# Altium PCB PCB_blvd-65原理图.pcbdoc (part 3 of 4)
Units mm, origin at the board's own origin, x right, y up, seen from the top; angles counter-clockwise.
Board outline 317.5 x 107.96 mm, 2 copper layers (Top Layer, Bottom Layer); 180 components, 111 nets, 404 pads, 231 vias.
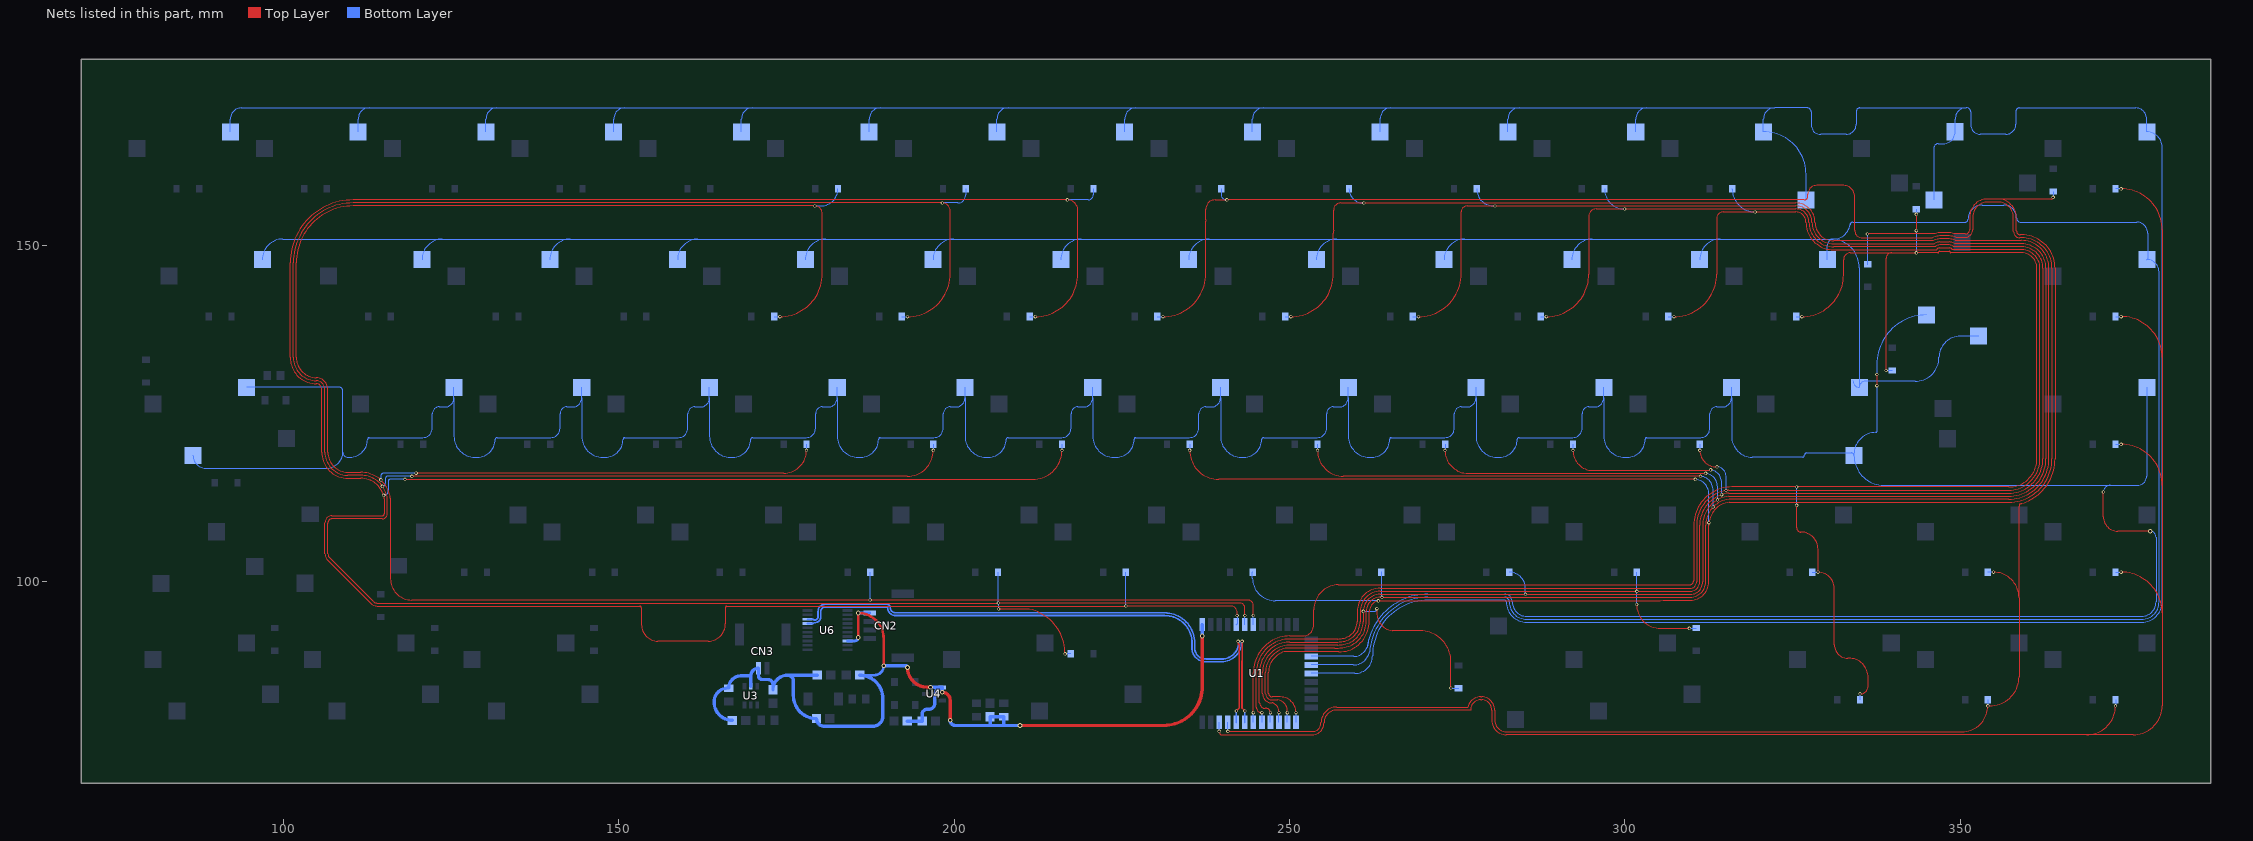
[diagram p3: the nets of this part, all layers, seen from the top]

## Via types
v1: diameter 0.5, hole 0.3, Top Layer to Bottom Layer, 198 vias
v2: diameter 0.7, hole 0.4, Top Layer to Bottom Layer, 33 vias

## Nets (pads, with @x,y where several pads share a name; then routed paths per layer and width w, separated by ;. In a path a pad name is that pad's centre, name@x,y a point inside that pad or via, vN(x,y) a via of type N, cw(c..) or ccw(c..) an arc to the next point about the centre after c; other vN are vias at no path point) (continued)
COL5: D5.2 D27.2 D43.2 D59.2 U1.7 | length 369.7
  Top Layer w0.1: 102.836,131.155 cw(c104.902,133.35) 101.887,133.35 101.887,147.447 cw(c110.385,147.447) 110.385,155.945 v1(179.208,155.945) cw(c179.208,154.813) 180.34,154.813 180.34,145.796 cw(c173.99,145.796) v1(173.99,139.446) ; 102.836,131.155 ccw(c104.902,133.35) 104.902,130.335 cw(c104.902,128.651) 106.586,128.655 cw(c104.046,128.651) 106.586,128.651 106.586,119.253 ccw(c109.601,119.253) 109.601,116.238 111.506,116.238 cw(c111.506,111.76) 113.037,115.969 cw(c111.506,111.76) 113.383,115.826 cw(c111.506,111.76) 113.689,115.671 cw(c111.506,111.76) v1(114.497,115.093) cw(c111.379,111.704) 115.779,113.065 cw(c111.379,111.704) 115.94,112.341 115.94,100.374 ccw(c119.126,100.374) 119.126,97.188 v1(187.476,97.188) 243.807,97.188 cw(c243.807,96.382) 244.613,96.382 v1(244.613,94.869) ; v1(119.761,116.089) 174.551,116.089 ccw(c174.551,119.507) v1(177.969,119.507)
  Bottom Layer w0.1: v1(114.497,115.093) 114.497,115.651 cw(c114.935,115.651) 114.935,116.089 v1(119.761,116.089) ; D27.2@173.143,139.446 v1(173.99,139.446) ; v1(177.969,119.507) D43.2@177.969,120.396 ; v1(179.208,155.945) 180.117,155.945 ccw(c180.117,158.496) D5.2@182.668,158.496 ; v1(187.476,97.188) 187.476,101.333 cw(c187.489,101.333) D59.2@187.489,101.346 ; U1.7@244.613,93.533 v1(244.613,94.869)
COL6: D6.2 D26.2 D42.2 D58.2 D74.2 U1.6 | length 439.9
  Top Layer w0.1: 106.136,128.651 106.136,119.253 ccw(c109.601,119.253) 109.468,115.791 ccw(c109.601,119.253) 109.601,115.788 111.506,115.788 cw(c111.506,111.76) 112.883,115.546 cw(c111.506,111.76) 113.194,115.418 cw(c111.506,111.76) 113.402,115.314 cw(c111.506,111.76) 113.469,115.278 cw(c111.506,111.76) 114.194,114.76 cw(c111.379,111.704) v1(114.742,114.145) cw(c111.379,111.704) 115.349,112.932 cw(c111.379,111.704) 115.49,112.308 115.49,110.029 cw(c114.739,110.029) 114.739,109.278 107.188,109.278 ccw(c107.188,108.712) 106.636,108.838 ccw(c107.823,108.654) 106.622,108.654 106.622,104.054 ccw(c107.313,104.054) 106.825,103.566 113.468,96.922 ccw(c113.912,97.367) 113.912,96.738 v1(206.589,96.738) 242.606,96.738 cw(c242.606,96.001) 243.343,96.001 v1(243.343,94.869) ; 106.136,128.654 ccw(c104.902,128.651) 104.902,129.885 cw(c104.902,133.35) 102.528,130.827 cw(c104.902,133.35) 101.437,133.35 101.437,147.447 cw(c110.385,147.447) 110.385,156.395 v1(198.241,156.395) cw(c198.241,155.246) 199.39,155.246 199.39,145.796 cw(c193.04,145.796) v1(193.04,139.446) ; v1(119.126,115.639) 193.024,115.639 ccw(c193.024,119.507) v1(196.892,119.507) ; v1(206.629,95.838) 211.211,95.838 cw(c209.677,89.154) v1(216.535,89.154)
  Bottom Layer w0.1: v1(114.742,114.145) ccw(c114.742,114.592) 115.189,114.592 115.189,115.316 cw(c115.512,115.316) 115.512,115.639 v1(119.126,115.639) ; D26.2@192.193,139.446 v1(193.04,139.446) ; v1(196.892,119.507) D42.2@196.892,120.396 ; v1(198.241,156.395) 200.539,156.395 ccw(c200.539,157.574) 201.427,156.799 ; D6.2@201.718,158.496 201.718,157.607 ; D58.2@206.539,101.346 cw(c206.539,101.296) 206.589,101.296 v1(206.589,96.738) cw(c206.589,96.698) 206.629,96.698 v1(206.629,95.838) ; v1(216.535,89.154) D74.2@217.383,89.154 ; U1.6@243.343,93.533 v1(243.343,94.869) ; 201.427,156.799 ccw(c200.539,157.574) 201.718,157.574 201.718,157.607 ; 201.427,156.799 ccw(c200.448,157.607) 201.718,157.607
COL7: D7.2 D25.2 D41.2 D57.2 U1.5 | length 475.6
  Top Layer w0.1: 105.686,128.651 105.686,119.253 ccw(c109.601,119.253) 109.601,115.338 111.506,115.338 cw(c111.506,111.76) 112.729,115.123 cw(c111.506,111.76) 113.006,115.009 cw(c111.506,111.76) 113.19,114.917 cw(c111.506,111.76) 113.25,114.885 cw(c111.506,111.76) 113.518,114.719 ; 105.686,128.653 ccw(c104.902,128.651) 104.902,129.435 cw(c104.902,133.35) 102.219,130.499 cw(c104.902,133.35) 100.987,133.35 100.987,147.447 cw(c110.385,147.447) 110.385,156.845 v1(216.875,156.845) cw(c216.875,155.28) 218.44,155.28 218.44,145.796 cw(c212.09,145.796) v1(212.09,139.446) ; v1(118.11,115.189) 211.751,115.189 ccw(c211.751,119.507) v1(216.069,119.507) ; v1(242.189,94.869) 242.189,95.388 ccw(c241.289,95.388) 241.289,96.288 v1(225.603,96.288) 166.12,96.288 ccw(c166.12,96.063) 165.895,96.063 165.895,93.631 cw(c163.322,93.631) 163.322,91.059 155.829,91.059 cw(c155.829,93.527) 153.362,93.527 153.362,96.043 ccw(c153.117,96.043) 153.117,96.288 113.993,96.288 cw(c113.993,97.646) 113.033,96.686 106.547,103.172 cw(c107.451,104.076) 106.172,104.076 106.172,108.712 cw(c107.188,108.712) 107.188,109.728 114.694,109.728 ccw(c114.694,110.075) 115.04,110.075 115.04,112.275 ; 113.518,114.719 cw(c111.506,111.76) 113.892,114.427 ; 113.518,114.719 cw(c111.506,111.76) 113.892,114.427 ; 113.892,114.427 cw(c111.379,111.704) 114.572,113.585 ; 113.892,114.427 cw(c111.379,111.704) 114.572,113.585 ; 114.572,113.585 cw(c111.379,111.704) v1(114.919,112.799) ; 114.572,113.585 cw(c111.379,111.704) v1(114.919,112.799) ; 114.572,113.585 cw(c111.379,111.704) v1(114.919,112.799) ; v1(114.919,112.799) cw(c111.379,111.704) 115.04,112.275 ; v1(114.919,112.799) cw(c111.379,111.704) 115.04,112.275 ; v1(114.919,112.799) cw(c111.379,111.704) 115.04,112.275
  Bottom Layer w0.1: v1(114.919,112.799) ccw(c114.919,113.519) 115.639,113.519 115.639,115.027 cw(c115.951,114.808) 115.951,115.189 v1(118.11,115.189) ; D25.2@211.243,139.446 v1(212.09,139.446) ; v1(216.069,119.507) D41.2@216.069,120.396 ; v1(216.875,156.845) 220.006,156.845 ccw(c220.006,157.607) 220.768,157.607 D7.2@220.768,158.496 ; D57.2@225.594,101.346 cw(c225.594,101.336) 225.603,101.336 v1(225.603,96.288) ; U1.5@242.073,93.533 ccw(c242.073,93.649) 242.189,93.649 v1(242.189,94.869)
COL8: D8.2 D24.2 D40.2 D56.2 U1.22 | length 454
  Top Layer w0.1: v1(231.14,139.446) ccw(c231.14,145.796) 237.49,145.796 237.49,153.67 cw(c240.665,153.67) 237.5,153.923 237.5,155.448 cw(c238.897,155.448) 238.897,156.845 v1(240.665,156.845) 326.771,156.845 ccw(c326.771,157.353) 327.279,157.353 327.279,157.682 cw(c328.601,157.682) 328.601,159.004 332.613,159.004 cw(c332.613,157.353) 334.264,157.353 334.264,152.328 ccw(c335.393,152.328) 335.393,151.199 345.853,151.199 cw(c346.964,149.098) 346.964,151.475 348.361,151.475 cw(c348.361,149.098) 349.356,151.257 350.716,151.257 ccw(c350.716,152.4) 351.859,152.4 351.859,154.305 cw(c354.076,154.305) 353.68,156.486 cw(c354.076,154.305) 354.076,156.522 355.6,156.522 cw(c355.6,154.178) 357.258,155.836 cw(c355.6,154.178) 357.944,154.178 357.944,152.157 ccw(c358.902,152.157) 358.902,151.199 359.178,151.199 cw(c359.178,146.685) 363.692,146.685 363.692,118.237 cw(c357.226,118.237) 357.226,111.771 355.786,111.771 cw(c355.356,120.132) 355.356,111.76 315.561,111.76 ; v1(235.119,119.507) ccw(c239.437,119.507) 239.437,115.189 v1(310.515,115.189) ; v1(250.963,80.391) ccw(c248.621,80.391) 248.621,82.734 247.434,82.734 cw(c247.434,83.304) 246.863,83.304 246.863,86.371 cw(c250.063,86.371) 249.215,89.457 257.373,89.457 ccw(c257.373,93.98) 261.896,93.98 261.896,95.457 cw(c263.525,95.457) v1(263.239,97.061) cw(c263.525,95.457) 263.525,97.086 304.858,97.086 ccw(c304.858,104.648) 305.7,97.133 309.753,97.133 ccw(c309.753,99.891) 312.511,99.891 312.511,108.331 cw(c315.976,108.331) v1(312.533,108.717) cw(c315.976,108.331) 312.635,109.25 cw(c315.976,108.331) 315.561,111.771
  Bottom Layer w0.1: D24.2@230.293,139.446 v1(231.14,139.446) ; v1(235.119,119.507) D40.2@235.119,120.396 ; D8.2@239.818,158.496 239.818,157.607 ccw(c240.58,157.607) 240.58,156.845 v1(240.665,156.845) ; D56.2@244.517,101.346 ccw(c244.517,101.305) 244.475,101.305 244.475,100.457 ccw(c247.872,100.457) 247.872,97.061 v1(263.239,97.061) ; U1.22@250.963,78.933 v1(250.963,80.391) ; v1(310.515,115.189) cw(c310.285,112.953) 312.533,112.918 v1(312.533,108.717)
COL9: D9.2 D23.2 D39.2 D55.2 U1.23 | length 383.6
  Top Layer w0.1: v1(249.682,80.391) 249.682,80.645 ccw(c248.031,80.645) 248.234,82.284 247.434,82.284 cw(c247.434,83.304) 246.413,83.304 246.413,86.371 cw(c250.063,86.371) 249.394,89.959 cw(c250.063,86.371) 249.61,89.993 256.744,89.993 ccw(c256.744,94.869) 257.281,90.023 ccw(c257.175,94.234) 257.745,90.06 ccw(c257.175,94.234) 258.153,90.136 ccw(c257.556,93.98) 261.446,93.98 261.446,95.504 cw(c263.525,95.504) 263.525,97.583 v1(263.786,97.583) 309.753,97.583 ccw(c309.753,99.891) 312.061,99.891 312.061,108.331 cw(c315.976,108.331) 312.201,109.369 cw(c315.976,108.331) v1(313.174,111.065) cw(c315.976,108.331) 315.535,112.221 357.226,112.221 ccw(c357.226,118.237) 363.242,118.237 363.242,146.685 ccw(c359.12,146.685) 359.12,150.807 349.252,150.807 ccw(c348.361,149.098) 348.361,151.025 346.964,151.025 ccw(c346.964,149.098) 345.971,150.749 331.147,150.749 cw(c331.147,153.543) 328.353,153.543 ccw(c325.501,153.543) 325.501,156.395 v1(261.073,156.395) 257.64,156.395 ccw(c257.64,155.321) 256.566,155.321 256.566,152.343 ccw(c261.073,151.863) 256.54,151.863 256.54,145.796 cw(c250.19,145.796) v1(250.19,139.446) ; v1(254.169,119.507) ccw(c258.037,119.507) 258.037,115.639 v1(311.277,115.639)
  Bottom Layer w0.1: D23.2@249.343,139.446 v1(250.19,139.446) ; v1(249.682,80.391) cw(c249.682,80.38) 249.693,80.38 U1.23@249.693,78.933 ; v1(254.169,119.507) D39.2@254.169,120.396 ; D9.2@258.868,158.496 ccw(c260.969,158.496) 260.969,156.395 v1(261.073,156.395) ; D55.2@263.694,101.346 cw(c263.694,101.254) 263.786,101.254 v1(263.786,97.583) ; v1(311.277,115.639) cw(c311.046,113.523) 313.174,113.488 v1(313.174,111.065)
COL10: D11.2 D22.2 D38.2 D54.2 D70.2 U1.24 | length 375.6
  Top Layer w0.1: v1(248.423,80.391) 248.423,80.507 ccw(c247.015,80.507) 247.487,81.834 247.434,81.834 cw(c247.434,83.304) 247.01,81.896 cw(c247.434,83.304) 245.963,83.304 245.963,86.371 cw(c250.063,86.371) 249.312,90.402 cw(c250.063,86.371) 250.063,90.471 257.175,90.471 ccw(c257.175,94.234) 257.684,90.506 ccw(c257.175,94.234) 258.066,90.578 ccw(c257.556,93.98) 260.996,93.98 v1(260.996,95.504) cw(c263.525,95.504) 263.525,98.033 v1(285.185,98.033) 309.753,98.033 ccw(c309.753,99.891) 311.611,99.891 311.611,108.331 cw(c315.976,108.331) 311.768,109.489 cw(c315.976,108.331) v1(313.824,112.129) cw(c315.976,108.331) 315.51,112.671 357.226,112.671 ccw(c357.226,118.237) 362.792,118.237 362.792,146.685 ccw(c359.178,146.685) 359.178,150.299 349.221,150.299 ccw(c348.361,149.098) 348.361,150.575 346.964,150.575 ccw(c346.964,149.098) 346.105,150.299 331.147,150.299 cw(c331.147,153.543) 327.903,153.543 ccw(c325.501,153.543) 327.136,155.303 ccw(c325.501,153.543) 325.501,155.945 v1(280.636,155.945) 276.468,155.945 ccw(c276.468,155.067) 275.59,155.067 275.59,145.796 cw(c269.24,145.796) v1(269.24,139.446) ; v1(263.017,95.885) ccw(c265.849,95.404) 265.303,92.583 269.494,92.583 cw(c269.494,88.011) 274.066,88.011 v1(274.066,84.074) ; v1(273.177,119.507) ccw(c276.606,119.507) 276.332,116.089 312.028,116.089 cw(c312.028,116.078) v1(312.039,116.078)
  Bottom Layer w0.1: U1.24@248.423,78.933 v1(248.423,80.391) ; v1(260.996,95.504) 262.636,95.504 ccw(c262.636,95.885) v1(263.017,95.885) ; D22.2@268.393,139.446 v1(269.24,139.446) ; v1(273.177,119.507) ccw(c273.177,119.549) 273.219,119.549 D38.2@273.219,120.396 ; v1(274.066,84.074) ccw(c274.108,84.074) 274.108,84.033 D70.2@275.209,84.033 ; D54.2@282.744,101.346 cw(c282.744,98.905) 285.185,98.905 v1(285.185,98.033) ; v1(312.039,116.078) cw(c311.807,114.074) 313.824,114.039 v1(313.824,112.129) ; D11.2@277.918,158.496 277.918,158.455 ccw(c280.416,158.455) 279.858,156.019 ; D11.2@277.918,158.496 ccw(c280.469,158.496) 279.858,156.019 ; D11.2@277.918,158.496 ccw(c280.469,158.496) 279.858,156.019 ; 279.858,156.019 ccw(c280.469,158.496) 280.469,155.945 cw(c280.469,158.496) 279.858,156.019
  other v1: 280.636,155.945
COL11: D12.2 D21.2 D37.2 D53.2 D69.2 U1.25 | length 323.1
  Top Layer w0.1: v1(247.153,80.391) ccw(c246.518,80.391) 246.518,81.026 246.38,81.026 cw(c246.38,81.893) 245.513,81.893 245.513,86.371 cw(c250.063,86.371) 249.229,90.844 cw(c250.063,86.371) 250.063,90.921 257.175,90.921 ccw(c257.175,94.234) 257.623,90.952 ccw(c257.175,94.234) 257.98,91.02 ccw(c257.556,93.98) 260.546,93.98 260.546,95.504 cw(c263.525,95.504) 263.525,98.483 v1(301.798,98.483) 309.753,98.483 ccw(c309.753,99.891) 311.161,99.891 311.161,108.331 cw(c315.976,108.331) 311.334,109.608 cw(c315.976,108.331) v1(314.447,112.897) cw(c315.976,108.331) 315.487,113.121 323.342,113.121 ; v1(288.29,139.446) ccw(c288.29,145.796) 294.64,145.796 294.64,154.432 cw(c295.703,154.432) 295.703,155.495 v1(299.972,155.495) 325.501,155.495 cw(c325.501,153.543) 326.83,154.974 cw(c325.501,153.543) 327.453,153.543 ; v1(292.269,119.507) ccw(c295.317,119.507) 294.623,116.539 312.754,116.539 ccw(c312.754,116.586) v1(312.801,116.586) ; v1(301.752,96.52) ccw(c305.308,96.52) 305.308,92.964 v1(309.626,92.964) ; 323.378,113.121 357.226,113.121 ccw(c357.226,118.237) 362.342,118.237 362.342,146.685 ccw(c359.178,146.685) 359.178,149.849 349.062,149.849 ccw(c348.361,149.098) 348.361,150.125 346.964,150.125 ccw(c346.964,149.098) 346.264,149.849 331.147,149.849 ; 327.453,153.543 ccw(c331.147,153.543) 331.147,149.849 ; 327.453,153.543 ccw(c331.147,153.543) 331.147,149.849
  Bottom Layer w0.1: U1.25@247.153,78.933 v1(247.153,80.391) ; D21.2@287.443,139.446 v1(288.29,139.446) ; v1(292.269,119.507) D37.2@292.269,120.396 ; D12.2@296.968,158.496 ccw(c299.969,158.496) 299.969,155.495 v1(299.972,155.495) ; v1(301.752,96.52) 301.752,98.437 v1(301.798,98.483) 301.798,101.341 ccw(c301.794,101.341) D53.2@301.794,101.346 ; v1(309.626,92.964) 310.601,92.964 ccw(c310.601,93.006) D69.2@310.642,93.006 ; v1(312.801,116.586) cw(c312.568,114.722) 314.447,114.687 v1(314.447,112.897)
COL12: D13.2 D20.2 D36.2 U1.26 | length 294.7
  Top Layer w0.1: v1(245.872,80.391) cw(c245.872,81.2) 245.063,81.2 245.063,86.371 cw(c250.063,86.371) 250.063,91.371 257.175,91.371 ccw(c257.175,94.234) 257.562,91.397 ccw(c257.175,94.234) 257.893,91.463 ccw(c257.556,93.98) 260.096,93.98 260.096,95.504 cw(c263.525,95.504) 263.525,98.933 309.753,98.933 ccw(c309.753,99.891) 310.711,99.891 310.711,108.331 cw(c315.976,108.331) 310.9,109.727 cw(c315.976,108.331) v1(315.093,113.521) cw(c315.976,108.331) 315.464,113.571 357.226,113.571 ccw(c357.226,118.237) 361.892,118.237 361.892,146.685 ccw(c359.178,146.685) 359.178,149.399 348.854,149.399 ccw(c348.361,149.098) 348.361,149.675 346.964,149.675 ccw(c346.964,149.098) 346.472,149.399 331.147,149.399 ; v1(307.34,139.446) ccw(c307.34,145.796) 313.69,145.796 313.69,154.051 cw(c314.684,154.051) 314.684,155.045 v1(319.433,155.045) 325.501,155.045 cw(c325.501,153.543) 326.523,154.644 cw(c325.501,153.543) 327.003,153.543 ; v1(311.192,119.507) ccw(c313.663,119.507) 313.663,117.036 v1(313.748,117.036) ; 327.003,153.543 ccw(c331.147,153.543) 331.147,149.399 ; 327.003,153.543 ccw(c331.147,153.543) 331.147,149.399 ; 327.003,153.543 ccw(c331.147,153.543) 331.147,149.399 ; 327.003,153.543 ccw(c331.147,153.543) 331.147,149.399
  Bottom Layer w0.1: v1(245.872,80.391) 245.872,78.944 ccw(c245.883,78.944) U1.26@245.883,78.933 ; D20.2@306.493,139.446 v1(307.34,139.446) ; v1(311.192,119.507) D36.2@311.192,120.396 ; v1(313.748,117.036) cw(c313.748,115.692) 315.093,115.692 v1(315.093,113.521) ; D13.2@316.018,158.496 D13.2@316.018,158.46 ; v1(319.433,155.045) cw(c319.433,158.46) 316.357,156.976 ; D13.2@316.018,158.455 D13.2@316.018,158.46 ; D13.2@316.018,158.455 ccw(c319.405,158.455) 316.29,157.123 ; D13.2@316.018,158.455 ccw(c319.405,158.455) 316.29,157.123 ; D13.2@316.018,158.46 ccw(c319.433,158.46) 316.29,157.123 ; D13.2@316.018,158.46 ccw(c319.433,158.46) 316.29,157.123 ; 316.29,157.123 ccw(c319.433,158.46) 316.357,156.976 ; 316.29,157.123 ccw(c319.405,158.455) 316.357,156.976 ; 316.29,157.123 ccw(c319.405,158.455) 316.357,156.976 ; 316.29,157.123 ccw(c319.433,158.46) 316.357,156.976 ; 316.357,156.976 ccw(c319.405,158.455) 319.405,155.067 cw(c319.405,158.455) 316.357,156.976
  other v1: 319.433,155.045
COL13: D14.2 D19.2 D35.2 D51.2 D67.2 U1.27 | length 284.2
  Top Layer w0.1: v1(244.613,80.391) 244.613,86.371 cw(c250.063,86.371) 250.063,91.821 251.968,91.821 ccw(c251.968,93.472) 253.619,93.472 253.619,95.758 cw(c257.302,95.758) 257.302,99.441 309.626,99.441 ccw(c309.626,100.076) 310.261,100.076 310.261,108.331 cw(c315.976,108.331) 315.976,114.046 v1(325.628,114.046) 357.251,114.046 ccw(c357.251,118.237) 361.442,118.237 361.442,146.685 ccw(c359.178,146.685) 359.178,148.949 348.591,148.949 cw(c348.591,149.052) 348.488,149.052 348.488,149.091 ; v1(325.628,111.31) 325.628,107.95 ccw(c326.263,107.95) 326.263,107.315 cw(c326.263,104.775) 328.803,104.775 v1(328.803,101.346) cw(c328.803,98.933) 331.216,98.933 331.216,90.551 ccw(c333.248,90.551) 333.248,88.519 333.375,88.519 cw(c333.375,85.598) 336.296,85.598 336.296,84.414 cw(c335.068,84.414) v1(335.068,83.185) ; v1(326.39,139.446) ccw(c326.39,145.669) 332.613,145.669 332.613,147.955 cw(c333.607,147.955) 333.607,148.949 339.791,148.949 ; v1(338.963,131.404) 338.963,148.122 cw(c339.791,148.122) 339.791,148.949 ; v1(343.463,152.273) v1(343.463,154.686) ; 348.488,149.098 ccw(c348.361,149.098) 348.361,149.225 346.964,149.225 ccw(c346.964,149.098) 346.837,149.098 cw(c346.688,149.098) 346.688,148.949 v1(343.472,148.949) 339.791,148.949
  Bottom Layer w0.1: U1.27@244.613,78.933 v1(244.613,80.391) ; D19.2@325.543,139.446 v1(326.39,139.446) ; v1(325.628,111.31) v1(325.628,114.046) ; D51.2@327.956,101.346 v1(328.803,101.346) ; D67.2@335.068,82.296 v1(335.068,83.185) ; v1(338.963,131.404) D35.2@339.852,131.404 ; v1(343.463,152.273) 343.463,148.958 ccw(c343.472,148.958) v1(343.472,148.949) ; v1(343.463,154.686) D14.2@343.463,155.472
COL14: D15.2 D18.2 D50.2 D66.2 U1.30 | length 253.9
  Top Layer w0.1: v1(240.792,77.597) 253.753,77.597 ccw(c253.365,78.867) 254.658,78.563 ccw(c253.365,78.867) 254.693,78.867 cw(c257.048,78.867) 257.048,81.222 276.589,81.222 cw(c278.511,80.772) 278.511,82.746 278.638,82.746 cw(c278.638,80.772) 280.612,80.772 280.612,79.248 ccw(c282.321,79.248) 282.321,77.539 350.25,77.539 ccw(c350.25,81.407) v1(354.118,81.407) 354.457,81.407 ccw(c354.457,85.725) 358.775,85.725 358.775,97.536 ; v1(336.169,151.765) 346.027,151.765 cw(c346.964,149.098) 346.964,151.925 348.361,151.925 cw(c348.361,149.098) 349.299,151.765 350.774,151.765 ccw(c350.774,152.4) 351.409,152.4 351.409,154.305 cw(c354.076,154.305) 354.076,156.972 355.6,156.972 ; v1(354.965,101.346) cw(c354.965,97.536) 358.775,97.536 ; v1(363.874,157.226) cw(c363.62,157.226) 363.62,156.972 355.6,156.972 ; 355.6,156.972 cw(c355.6,154.178) 358.394,154.178 358.394,152.226 ccw(c358.971,152.226) 358.971,151.649 359.178,151.649 cw(c359.178,146.685) 364.142,146.685 364.142,118.237 cw(c357.226,118.237) 360.941,112.403 cw(c357.226,118.237) 359.858,111.842 cw(c357.226,118.237) 359.18,111.603 cw(c357.226,118.237) 358.971,111.545 ccw(c359.18,111.198) 358.775,111.198 358.775,97.536
  Bottom Layer w0.1: v1(240.792,77.597) 240.792,78.922 U1.30@240.803,78.933 ; v1(336.169,151.765) 336.169,147.303 ccw(c336.207,147.303) D18.2@336.207,147.266 ; v1(354.118,81.407) D66.2@354.118,82.296 ; D50.2@354.118,101.346 v1(354.965,101.346) ; v1(363.874,157.226) D15.2@363.874,158.099
COL15: D16.2 D17.2 D33.2 D49.2 D65.2 U1.31 | length 271.7
  Top Layer w0.1: v1(239.522,77.597) 239.522,77.481 ccw(c239.914,77.481) 239.914,77.089 253.365,77.089 ccw(c253.365,78.867) 255.143,78.867 cw(c257.048,78.867) 257.048,80.772 276.987,80.772 cw(c278.511,80.772) 278.511,82.296 278.638,82.296 cw(c278.638,80.772) 280.162,80.772 280.162,79.248 ccw(c282.321,79.248) 282.321,77.089 368.85,77.089 ; v1(373.168,81.407) cw(c368.85,81.407) 368.85,77.089 ; v1(374.015,101.346) cw(c374.015,95.25) 380.111,95.25 ; v1(374.015,120.396) cw(c374.015,114.3) 380.111,114.3 ; v1(374.015,139.446) cw(c374.015,133.35) 380.111,133.35 ; v1(374.015,158.496) cw(c374.015,152.4) 380.111,152.4 380.111,133.35 ; 368.85,77.089 375.793,77.089 ccw(c375.793,81.407) 380.111,81.407 380.111,95.25 ; 380.111,95.25 380.111,114.3 ; 380.111,114.3 380.111,133.35
  Bottom Layer w0.1: v1(239.522,77.597) 239.522,78.922 U1.31@239.533,78.933 ; v1(373.168,81.407) D65.2@373.168,82.296 ; D49.2@373.168,101.346 v1(374.015,101.346) ; D33.2@373.168,120.396 v1(374.015,120.396) ; D17.2@373.168,139.446 v1(374.015,139.446) ; D16.2@373.168,158.496 v1(374.015,158.496)
DCLK: U1.29 U6.8 | length 85
  Top Layer w0.254: v1(242.073,80.645) 242.505,81.077 242.505,90.493 242.346,90.652 v1(242.346,91.029)
  Bottom Layer w0.254: U6.8@178.101,94.335 178.975,94.335 179.097,94.213 179.224,94.213 ccw(c179.224,94.694) 179.705,94.694 179.705,95.504 cw(c180.746,95.504) 180.746,96.545 189.992,96.545 cw(c189.992,96.076) 190.462,96.076 ccw(c191.262,96.076) 191.262,95.275 231.394,95.275 cw(c231.394,90.805) 235.864,90.805 235.864,90.018 ccw(c237.49,90.018) 237.49,88.392 239.903,88.392 ccw(c239.903,90.932) 242.443,90.932 v1(242.346,91.029) ; U1.29@242.073,78.933 v1(242.073,80.645)
DIO: U1.28 U6.7 | length 85.6
  Top Layer w0.254: v1(242.946,91.029) 242.946,88.173 cw(c242.911,88.173) 242.911,88.138 242.911,81.077 v1(243.343,80.645)
  Bottom Layer w0.254: U6.7@178.101,93.685 178.975,93.685 179.097,93.807 179.224,93.807 ccw(c179.224,94.694) 180.111,94.694 180.111,95.504 cw(c180.746,95.504) 180.746,96.139 189.992,96.139 cw(c189.992,96.076) 190.056,96.076 ccw(c191.262,96.076) 191.262,94.869 231.394,94.869 cw(c231.394,90.805) 235.458,90.805 235.458,90.018 ccw(c237.49,90.018) 237.49,87.986 239.903,87.986 ccw(c239.903,90.932) 242.849,90.932 v1(242.946,91.029) ; U1.28@243.343,78.933 v1(243.343,80.645)
GND: C1.1 C6.1 C7.1 C8.2 C9.1 C10.1 C11.1 C12.1 CN2.1 CN3.1 R2.2 R4.2 U1.1 U3.2 U4.1 U6.18 | length 158.4
  Top Layer w0.4: v2(185.695,91.593) v2@185.695,95.23 ; v2(189.484,87.376) 189.484,91.44 ccw(c185.674,91.44) v2(185.674,95.25) ; v2(185.674,95.25) cw(c185.674,95.23) v2@185.695,95.23 ; v2(185.674,95.25) cw(c185.674,95.23) v2@185.695,95.23
  Top Layer w0.5: v2(193.04,87.122) ccw(c195.961,87.122) 195.961,84.201 v2(196.469,84.201) ; v2(198.212,83.439) cw(c198.212,82.261) 199.39,82.261 v2(199.39,79.248) ; v2(209.804,78.486) 231.267,78.486 ccw(c231.267,84.201) 236.982,84.201 v2@236.982,91.567
  Bottom Layer w0.4: U6.18@184.098,91.085 185.187,91.085 ccw(c185.187,91.593) v2(185.695,91.593) ; v2(185.674,95.25) CN2.1@187.428,95.25 ; C12.1@185.912,85.979 188.087,85.979 ccw(c188.087,87.376) v2(189.484,87.376)
  Bottom Layer w0.5: C6.1@166.894,79.248 cw(c166.894,81.931) 164.211,81.931 164.211,82.042 cw(c166.227,82.042) 166.227,84.058 R2.2@166.37,84.058 cw(c168.183,84.058) 168.183,85.87 169.672,85.87 ; U3.2@169.672,84.331 169.672,85.87 ; C11.1@179.594,85.979 175.149,85.979 ; C12.1@185.912,85.979 185.912,85.963 cw(c185.912,82.518) 189.357,82.518 189.357,79.817 cw(c187.899,79.817) 187.899,78.359 180.61,78.359 cw(c180.61,79.502) C1.1@179.467,79.502 cw(c179.467,82.947) 176.022,82.947 176.022,85.106 ccw(c175.149,85.106) 175.149,85.979 ; v2(189.484,87.376) 192.786,87.376 cw(c192.786,87.122) v2(193.04,87.122) ; C9.1@193.024,79.121 C10.1@195.215,79.121 195.215,80.137 cw(c195.977,80.137) 195.977,80.899 196.215,80.899 ccw(c196.215,81.788) 197.104,81.788 197.104,83.058 cw(c198.181,83.058) 198.181,84.135 U4.1@198.212,84.135 ; v2(196.469,84.201) 198.146,84.201 cw(c198.146,84.135) U4.1@198.212,84.135 ; v2(198.212,83.439) U4.1@198.212,84.135 ; v2(199.39,79.248) ccw(c200.152,79.248) 200.152,78.486 205.377,78.486 ; v2(209.804,78.486) 207.447,78.486 ; v2(236.982,91.821) 236.982,93.522 cw(c236.993,93.522) U1.1@236.993,93.533 ; 169.672,85.87 cw(c170.829,85.87) CN3.1@170.829,87.027 170.829,85.852 ccw(c171.337,85.852) 171.337,85.344 172.212,85.344 cw(c172.212,84.582) 172.974,84.582 C7.1@172.974,83.804 cw(c175.149,83.804) 175.149,85.979 ; 205.377,78.486 207.447,78.486 ; 205.377,78.486 cw(c205.377,78.504) 205.359,78.504 C8.2@205.359,79.772 R4.2@207.391,79.772 207.391,78.542 ccw(c207.447,78.542) 207.447,78.486
  other v2: 185.695,91.593
ROW0: KEY00.ROW KEY01.ROW KEY02.ROW KEY03.ROW KEY04.ROW KEY05.ROW KEY06.ROW KEY07.ROW KEY08.ROW KEY09.ROW KEY010.ROW KEY011.ROW KEY012.ROW KEY013.ROW KEY014.ROW KEY014_CP.ROW KEY015.ROW U1.17 | length 596.4
  Bottom Layer w0.1: KEY00.ROW@92.075,167.006 92.075,168.91 cw(c93.726,168.91) 93.726,170.561 112.776,170.561 ; KEY01.ROW@111.125,167.006 111.125,168.91 cw(c112.776,168.91) 112.776,170.561 ; KEY02.ROW@130.175,167.006 130.175,168.91 cw(c131.826,168.91) 131.826,170.561 ; KEY03.ROW@149.225,167.006 149.225,168.91 cw(c150.876,168.91) 150.876,170.561 ; KEY04.ROW@168.275,167.006 168.275,168.91 cw(c169.926,168.91) 169.926,170.561 ; KEY05.ROW@187.324,167.006 187.324,168.91 cw(c188.975,168.91) 188.975,170.561 ; KEY06.ROW@206.373,167.006 ccw(c206.373,167.008) 206.375,167.008 206.375,168.91 cw(c208.026,168.91) 208.026,170.561 ; KEY07.ROW@225.425,167.006 225.425,168.91 cw(c227.076,168.91) 227.076,170.561 ; KEY08.ROW@244.475,167.006 244.475,168.91 cw(c246.126,168.91) 246.126,170.561 ; U1.17@253.227,86.233 259.715,86.233 ccw(c259.715,88.9) 262.382,88.9 cw(c270.637,88.9) 270.637,97.155 282.067,97.155 cw(c282.067,96.901) 282.321,96.901 ccw(c285.369,96.901) 285.369,93.853 377.063,93.853 ccw(c377.063,96.901) 380.111,96.901 380.111,164.719 ccw(c377.825,164.719) KEY015.ROW@377.825,167.006 377.825,168.91 ccw(c376.174,168.91) 376.174,170.561 358.826,170.561 ccw(c358.826,170.053) 358.318,170.053 358.318,168.148 cw(c356.794,168.148) 356.794,166.624 352.984,166.624 cw(c352.984,168.021) 351.587,168.021 351.587,169.968 ccw(c350.994,169.968) 350.994,170.561 350.901,170.561 ; KEY09.ROW@263.525,167.006 263.525,169.037 cw(c265.049,169.037) 265.049,170.561 ; KEY010.ROW@282.575,167.005 282.575,168.91 cw(c284.226,168.91) 284.226,170.561 ; KEY011.ROW@301.625,167.006 301.625,168.91 cw(c303.276,168.91) 303.276,170.561 ; 322.326,170.56 ccw(c322.326,168.909) 320.675,168.909 KEY012.ROW@320.675,167.005 cw(c320.675,160.655) 327.025,160.655 KEY013.ROW@327.025,156.845 ; KEY014.ROW@346.075,156.845 346.075,164.592 cw(c346.71,164.592) 346.71,165.227 347.467,165.227 ccw(c347.467,167.01) KEY014_CP.ROW@349.25,167.01 349.25,168.91 cw(c350.901,168.91) 350.901,170.561 ; 112.776,170.561 131.826,170.561 ; 131.826,170.561 150.876,170.561 ; 150.876,170.561 169.926,170.561 ; 169.926,170.561 188.975,170.561 ; 188.975,170.561 208.026,170.561 ; 208.026,170.561 227.076,170.561 ; 227.076,170.561 246.126,170.561 ; 246.126,170.561 265.049,170.561 ; 265.049,170.561 284.226,170.561 ; 284.226,170.561 303.276,170.561 ; 303.276,170.561 322.326,170.561 327.194,170.561 cw(c327.194,169.968) 327.787,169.968 327.787,168.021 ccw(c329.184,168.021) 329.184,166.624 332.994,166.624 ccw(c332.994,168.148) 334.518,168.148 334.518,170.053 cw(c335.026,170.053) 335.026,170.561 350.901,170.561
ROW1: KEY10.ROW KEY12.ROW KEY13.ROW KEY14.ROW KEY15.ROW KEY16.ROW KEY17.ROW KEY18.ROW KEY19.ROW KEY110.ROW KEY111.ROW KEY112.ROW KEY113.ROW KEY114.ROW KEY114_CP.ROW KEY115.ROW U1.16 | length 584.7
  Bottom Layer w0.1: KEY10.ROW@96.838,147.956 cw(c99.885,147.956) 99.885,151.003 123.697,151.003 ; KEY12.ROW@120.65,147.956 cw(c123.697,147.956) 123.697,151.003 ; KEY13.ROW@139.7,147.955 cw(c142.748,147.955) 142.748,151.003 ; KEY14.ROW@158.75,147.955 cw(c161.798,147.955) 161.798,151.003 ; KEY15.ROW@177.8,147.955 cw(c180.848,147.955) 180.848,151.003 ; KEY16.ROW@196.85,147.955 cw(c199.899,147.955) 199.899,151.003 ; KEY17.ROW@215.9,147.955 cw(c218.949,147.955) 218.949,151.003 ; KEY18.ROW@234.95,147.955 cw(c237.999,147.955) 237.999,151.003 ; U1.16@253.227,87.503 259.515,87.503 ccw(c259.515,89.988) 261.953,89.507 ; KEY19.ROW@254,147.955 cw(c257.048,147.955) 257.048,151.003 ; KEY110.ROW@273.05,147.955 cw(c276.098,147.955) 276.098,151.003 ; KEY111.ROW@292.1,147.955 cw(c295.149,147.955) 295.149,151.003 ; KEY112.ROW@311.15,147.955 cw(c314.199,147.955) 314.199,151.003 ; KEY113.ROW@330.2,147.955 330.2,150.114 cw(c331.089,150.114) 330.97,150.995 ; KEY114_CP.ROW@334.01,129.857 ccw(c334.962,129.857) KEY114_CP.ROW@334.962,128.905 ; KEY114.ROW@352.745,136.522 350.01,136.522 ccw(c350.01,133.35) 346.837,133.35 cw(c343.281,133.35) 343.281,129.794 335.851,129.794 ccw(c335.851,128.905) KEY114_CP.ROW@334.962,128.905 ; 123.697,151.003 142.748,151.003 ; 142.748,151.003 161.798,151.003 ; 161.798,151.003 180.848,151.003 ; 180.848,151.003 199.899,151.003 ; 199.899,151.003 218.949,151.003 ; 218.949,151.003 237.999,151.003 ; 237.999,151.003 257.048,151.003 ; 257.048,151.003 276.098,151.003 ; 261.953,89.507 cw(c270.637,88.9) 262.001,89.988 ; 261.953,89.507 cw(c270.637,88.9) 262.001,89.988 ; 261.953,89.507 cw(c270.637,88.9) 262.001,89.988 ; 262.001,89.988 cw(c270.637,88.9) 270.637,97.605 282.067,97.605 cw(c282.067,96.901) 282.771,96.901 ccw(c285.369,96.901) 285.369,94.303 377.063,94.303 ccw(c377.063,96.901) 379.661,96.901 379.661,146.119 ccw(c377.825,146.119) KEY115.ROW@377.825,147.955 ccw(c377.825,148.082) 377.952,148.082 377.952,151.892 ccw(c376.301,151.892) 376.301,153.543 359.029,153.543 cw(c359.029,154.178) 358.394,154.178 ccw(c356.489,154.178) 356.489,156.083 353.314,156.083 ccw(c353.314,153.924) 351.155,153.924 cw(c350.774,153.924) 350.774,153.543 333.981,153.543 ccw(c333.981,153.163) 333.614,153.261 ; 276.098,151.003 295.149,151.003 ; 295.149,151.003 314.199,151.003 ; 314.199,151.003 330.708,151.003 ; 330.708,151.003 331.089,151.003 ; 330.708,151.003 cw(c330.708,146.749) 330.97,150.995 ; 330.97,150.995 cw(c330.708,146.749) 334.962,146.749 KEY114_CP.ROW@334.962,128.905 ; 330.97,150.995 cw(c331.089,150.114) 331.089,151.003 ; 331.089,151.003 ccw(c331.089,153.543) 333.601,153.163 ; 333.601,153.163 cw(c333.981,153.163) 333.614,153.261 ; 333.601,153.163 ccw(c331.089,153.543) 333.614,153.261
ROW2: KEY20.ROW KEY20_CP.ROW KEY22.ROW KEY23.ROW KEY24.ROW KEY25.ROW KEY26.ROW KEY27.ROW KEY28.ROW KEY29.ROW KEY210.ROW KEY211.ROW KEY212.ROW KEY213.ROW KEY213_CP.ROW KEY215.ROW U1.15 | length 687.8
  Top Layer w0.1: v1(337.566,129.159) v1(337.566,130.81) ; v1(371.348,113.284) 371.348,109.601 ccw(c373.507,109.601) 373.507,107.442 v2(378.333,107.442)
  Bottom Layer w0.1: KEY20.ROW@86.487,118.745 ccw(c88.393,118.745) 88.393,116.84 106.426,116.84 ccw(c106.426,119.253) 108.743,118.579 ccw(c106.426,119.253) 108.839,119.253 ; KEY20_CP.ROW@94.488,128.905 108.332,128.905 cw(c108.332,128.397) 108.839,128.397 108.839,119.253 ; 108.839,119.131 108.839,119.253 ; KEY22.ROW@125.413,128.895 125.413,127.313 ; KEY23.ROW@144.463,128.895 144.463,127.313 ; KEY24.ROW@163.513,128.895 163.513,127.313 ; KEY25.ROW@182.563,128.895 182.563,127.313 ; KEY26.ROW@201.613,128.895 201.613,127.313 ; KEY27.ROW@220.663,128.895 220.663,127.313 ; KEY28.ROW@239.713,128.895 239.713,127.313 ; U1.15@253.227,88.773 259.569,88.773 ccw(c259.569,90.91) 261.569,90.158 cw(c270.637,88.9) 261.706,90.91 ; KEY29.ROW@258.763,128.895 258.763,127.313 ; 261.881,91.572 ccw(c270.637,88.9) 261.598,90.349 cw(c270.637,88.9) 265.081,96.176 cw(c270.637,88.9) 270.637,98.055 282.067,98.055 cw(c282.067,96.901) 283.221,96.901 ccw(c285.369,96.901) 285.369,94.753 377.063,94.753 ccw(c377.063,96.901) 379.211,96.901 379.211,106.564 ccw(c378.333,106.564) v2(378.333,107.442) ; KEY210.ROW@277.813,128.895 277.813,127.313 ; KEY211.ROW@296.863,128.895 296.863,127.313 ; KEY212.ROW@315.913,128.895 315.913,127.313 ; v1(337.566,129.159) 337.566,122.301 cw(c337.439,122.301) 337.439,122.174 ccw(c337.439,118.904) 334.169,118.904 KEY213.ROW@334.169,118.742 ; v1(337.566,130.81) 337.566,132.299 cw(c344.964,132.299) KEY213_CP.ROW@344.964,139.697 ; v1(371.348,113.284) cw(c372.364,113.284) 372.364,114.3 ; KEY215.ROW@377.825,128.905 377.825,115.67 cw(c376.455,115.67) 376.455,114.3 372.364,114.3 ; 108.839,119.253 ccw(c109.601,119.253) 109.601,118.491 109.86,118.491 ccw(c109.86,121.158) 112.527,121.158 cw(c112.781,121.158) 112.781,121.412 120.782,121.412 ccw(c120.782,122.809) 122.179,122.809 122.179,124.968 cw(c123.195,124.968) 123.195,125.984 124.084,125.984 ccw(c124.084,127.313) 125.413,127.313 ; 125.413,127.313 125.413,121.608 ccw(c128.529,121.608) 128.529,118.491 128.91,118.491 ccw(c128.91,121.158) 131.577,121.158 cw(c131.831,121.158) 131.831,121.412 139.832,121.412 ccw(c139.832,122.809) 141.229,122.809 141.229,124.968 cw(c142.245,124.968) 142.245,125.984 143.134,125.984 ccw(c143.134,127.313) 144.463,127.313 ; 144.463,127.313 144.463,121.608 ccw(c147.579,121.608) 147.579,118.491 147.96,118.491 ccw(c147.96,121.158) 150.627,121.158 cw(c150.881,121.158) 150.881,121.412 158.882,121.412 ccw(c158.882,122.809) 160.279,122.809 160.279,124.968 cw(c161.295,124.968) 161.295,125.984 162.184,125.984 ccw(c162.184,127.313) 163.513,127.313 ; 163.513,127.313 163.513,121.608 ccw(c166.629,121.608) 166.629,118.491 167.01,118.491 ccw(c167.01,121.158) 169.677,121.158 cw(c169.931,121.158) 169.931,121.412 177.932,121.412 ccw(c177.932,122.809) 179.329,122.809 179.329,124.968 cw(c180.345,124.968) 180.345,125.984 181.234,125.984 ccw(c181.234,127.313) 182.563,127.313 ; 182.563,127.313 182.563,121.608 ccw(c185.679,121.608) 185.679,118.491 186.06,118.491 ccw(c186.06,121.158) 188.727,121.158 cw(c188.981,121.158) 188.981,121.412 196.982,121.412 ccw(c196.982,122.809) 198.379,122.809 198.379,124.968 cw(c199.395,124.968) 199.395,125.984 200.284,125.984 ccw(c200.284,127.313) 201.613,127.313 ; 201.613,127.313 201.613,121.608 ccw(c204.729,121.608) 204.729,118.491 205.11,118.491 ccw(c205.11,121.158) 207.777,121.158 cw(c208.031,121.158) 208.031,121.412 216.032,121.412 ccw(c216.032,122.809) 217.429,122.809 217.429,124.968 cw(c218.445,124.968) 218.445,125.984 219.334,125.984 ccw(c219.334,127.313) 220.663,127.313 ; 220.663,127.313 220.663,121.608 ccw(c223.779,121.608) 223.779,118.491 224.16,118.491 ccw(c224.16,121.158) 226.827,121.158 cw(c227.081,121.158) 227.081,121.412 235.082,121.412 ccw(c235.082,122.809) 236.479,122.809 236.479,124.968 cw(c237.495,124.968) 237.495,125.984 238.384,125.984 ccw(c238.384,127.313) 239.713,127.313 ; 239.713,127.313 239.713,121.608 ccw(c242.829,121.608) 242.829,118.491 243.21,118.491 ccw(c243.21,121.158) 245.877,121.158 cw(c246.131,121.158) 246.131,121.412 254.132,121.412 ccw(c254.132,122.809) 255.529,122.809 255.529,124.968 cw(c256.545,124.968) 256.545,125.984 257.434,125.984 ccw(c257.434,127.313) 258.763,127.313 ; 258.763,127.313 258.763,121.608 ccw(c261.879,121.608) 261.879,118.491 262.26,118.491 ccw(c262.26,121.158) 264.927,121.158 cw(c265.181,121.158) 265.181,121.412 273.182,121.412 ccw(c273.182,122.809) 274.579,122.809 274.579,124.968 cw(c275.595,124.968) 275.595,125.984 276.484,125.984 ccw(c276.484,127.313) 277.813,127.313 ; 277.813,127.313 277.813,121.608 ccw(c280.929,121.608) 280.929,118.491 281.31,118.491 ccw(c281.31,121.158) 283.977,121.158 cw(c284.231,121.158) 284.231,121.412 292.232,121.412 ccw(c292.232,122.809) 293.629,122.809 293.629,124.968 cw(c294.645,124.968) 294.645,125.984 295.534,125.984 ccw(c295.534,127.313) 296.863,127.313 ; 296.863,127.313 296.863,121.608 ccw(c299.979,121.608) 299.979,118.491 300.36,118.491 ccw(c300.36,121.158) 303.027,121.158 cw(c303.281,121.158) 303.281,121.412 311.282,121.412 ccw(c311.282,122.809) 312.679,122.809 312.679,124.968 cw(c313.695,124.968) 313.695,125.984 314.584,125.984 ccw(c314.584,127.313) 315.913,127.313 ; 315.913,127.313 315.913,121.608 ccw(c319.029,121.608) 319.029,118.491 326.517,118.491 ccw(c326.517,118.745) 326.771,118.745 cw(c327.152,118.745) 327.152,119.126 333.785,119.126 cw(c333.785,118.742) KEY213.ROW@334.169,118.742 ; KEY213.ROW@334.169,118.742 ccw(c338.611,118.742) 338.611,114.3 372.364,114.3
